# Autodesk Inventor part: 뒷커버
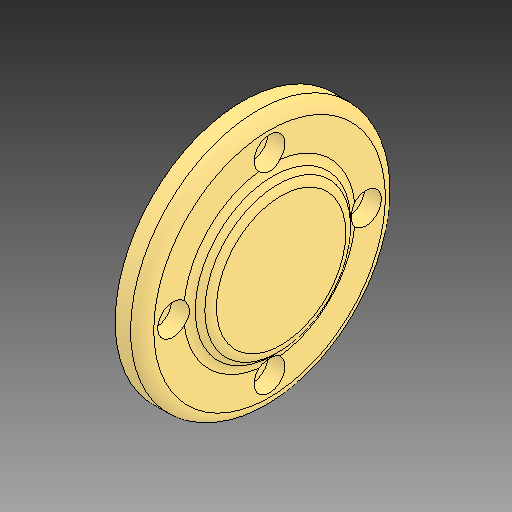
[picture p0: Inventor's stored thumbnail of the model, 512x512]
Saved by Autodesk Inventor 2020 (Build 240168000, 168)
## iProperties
Created: 2025-03
Part Number: 뒷커버
Material: 알루미늄 6061
Document SubType Name: Modeling
Designer: CA01
Density: 2.7 g/cm^3
Appearance: 기본값
Author: jhkim
Sending System: Autodesk Inventor 2025
Preprocessor: ST-DEVELOPER v20
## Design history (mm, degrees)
feature "솔리드1"
node "솔리드2"
